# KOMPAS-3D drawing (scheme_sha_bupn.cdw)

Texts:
  Шкаф автоматики   Схема электрическая соединений
  Мерекин С.А.
  Текст на чертеже
  Размерные надписи
  Шероховатость
  Линия-выноска #1
  Линия-выноска #2
  Линия-выноска #3
  Отклонения формы и база
  Заголовок таблицы
  Ячейка таблицы
  Стрелка вида
  Обозначение изменения
  Фигурная скобка
  Номер узла
  Марка координационной оси
  VRCB
  Выносная надпись
  Обозначение узла
  Марка/позиционное обозначение с линией-выноской
  Марка/позиционное обозначение на линии
  Марка/позиционное обозначение без линии-выноски
  Разъёмы связи с БУПН
  ХТ1
  Цепь
  Конт.
  Фаза
  Ноль
  SF1
  SF2
  Коммутация цепей переключателя SA
  "Авт."
  "0ткл."
  "Ручн."
  "ЗД  ПН"
  ХТ2
  Сигнализация
  АВАРИЯ
  КПШ
  ХТ4
  Фаза ЭЗ
  Закр. ЭЗ
  Откр. ЭЗ
  "СЕТЬ"
  HLG
  SBC
  "Пуск"
  ХТ6
  КПШ (Пуск)
  Датчик аварии ЭЗ
  ХТ5
  Адрес
  ДПД1
  Пожарный
  насос № 1
  ДПД2
  насос № 2
  ХТ3
  МП1
  FМП1
  МП2
  FМП2
  "Авария"
  HLR
  от АВР
  Задвижка
  Фаза ручн.
  Кнопка поэтажного
  шлейфа (КПШ)
  XTA
  XTB
  Земля
  "СЕТЬ
  III
  Дверца шкафа автоматики
  CONTINUOUS0
  Стили документа
  Шкаф автоматики
  Схема электрическая
  соединений
  Никулов Н.Ю.
  Федюкин А.С.
  ООО
  "ЭТК-Прибор"
  типа ША БУПН
Dimensions and other numbers on the sheet: 7; 1; 3; 2; 4; 5; 6; 0,2; 0,4; 0,3; 0; 8; 9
